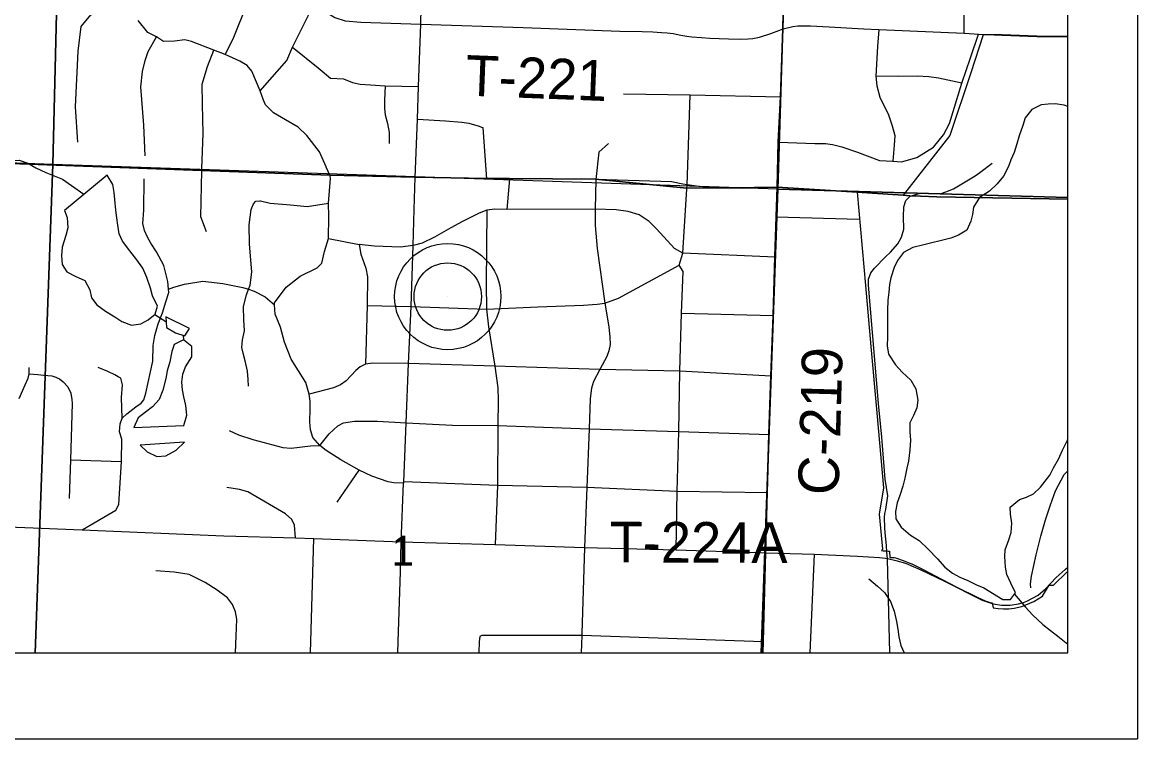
# Model space of a CAD drawing. Extents: x 0 to 34, y 0 to 22.
# Drawn here: x 8.174 to 9.735, y 14 to 15.003 of the extents above; entities that cross this region are included whole.
import ezdxf

# ---------------------------------------------------------------- set-up
doc = ezdxf.new("R2010")
doc.units = 0
for name, color, linetype in [('GM_X_City_Street', 7, 'Continuous'), ('GM_X_Corporation', 7, 'Continuous'), ('GM_X_County_Road', 7, 'Continuous'), ('GM_X_County_Road_Text', 7, 'Continuous'), ('GM_X_Major_Lake', 7, 'Continuous'), ('GM_X_Minor_Lake', 7, 'Continuous'), ('GM_X_Minor_River', 7, 'Continuous'), ('GM_X_Section_Text', 7, 'Continuous'), ('GM_X_Township_Road', 7, 'Continuous'), ('GM_X_Township_Road_Text', 7, 'Continuous'), ('GM_X_Unincorporated', 7, 'Continuous'), ('GM_X_Unincorporated_Location', 7, 'Continuous'), ('SH_Data', 7, 'Continuous')]:
    doc.layers.add(name, color=color, linetype=linetype)

msp = doc.modelspace()

# ---------------------------------------------------------------- linework, layer by layer
at = {"layer": 'GM_X_City_Street'}
for points in [[(9.3822, 14.3208), (9.385, 14.3403), (9.3814, 14.3634), (9.3768, 14.4223), (9.3723, 14.4696), (9.3581, 14.6353), (9.3583, 14.6433), (9.3616, 14.6525), (9.3665, 14.6588), (9.382, 14.675), (9.3888, 14.6815), (9.399, 14.693), (9.4045, 14.7025), (9.4075, 14.7137), (9.4072, 14.7307), (9.4075, 14.7449), (9.4105, 14.7535), (9.4164, 14.7599), (9.4304, 14.7639), (9.4497, 14.7634), (9.4584, 14.7629), (9.4664, 14.7659), (9.4769, 14.7701), (9.5076, 14.7883), (9.514, 14.7928), (9.5313, 14.8061)], [(9.5854, 14.2112), (9.585, 14.2171), (9.5864, 14.2277), (9.5926, 14.2575), (9.5992, 14.2836), (9.6061, 14.3065), (9.6127, 14.3274), (9.6201, 14.3472), (9.632, 14.3698), (9.637, 14.3752)]]:
    msp.add_lwpolyline(points, dxfattribs=at)
at = {"layer": 'GM_X_Corporation'}
for points in [[(7.1023, 20.9204), (2.837, 20.9204), (2.837, 14.1204), (9.637, 14.1204), (9.637, 20.9204), (9.4036, 20.9204), (9.4022, 20.8667), (9.2273, 20.8723), (9.1354, 20.8749), (9.124, 20.8753), (8.9858, 20.878), (8.9676, 20.8785), (8.8663, 20.881), (8.6259, 20.8892), (8.5535, 20.8914), (8.5421, 20.8915), (8.4667, 20.8934), (8.0602, 20.9055), (7.9522, 20.9084), (7.1104, 20.9188)], [(8.2409, 15.8234), (8.2165, 14.8042), (7.2089, 14.8416), (7.2356, 15.8559)], [(8.2409, 15.8234), (9.2625, 15.7858), (9.2313, 14.7696), (8.2165, 14.8042)], [(9.637, 14.7579), (9.637, 15.7721), (9.2625, 15.7858), (9.2313, 14.7696)], [(9.637, 14.234), (9.637, 14.9831), (9.5936, 14.9839), (9.545, 14.9856), (9.5186, 14.9858), (9.5013, 14.9322), (9.4722, 14.8448), (9.4066, 14.7611), (9.3424, 14.7652), (9.354, 14.6346), (9.3616, 14.5494), (9.3699, 14.4562), (9.3793, 14.3514), (9.373, 14.3145), (9.3776, 14.2655), (9.3765, 14.2634), (9.3785, 14.2633), (9.3808, 14.2632), (9.3837, 14.263), (9.3859, 14.2627), (9.3874, 14.2625), (9.388, 14.2539), (9.3941, 14.2537), (9.3957, 14.2533), (9.4001, 14.2521), (9.4091, 14.2488), (9.4162, 14.2459), (9.4188, 14.2448), (9.4337, 14.2373), (9.4613, 14.223), (9.4808, 14.2129), (9.5113, 14.1976), (9.5214, 14.193), (9.5284, 14.1908), (9.5313, 14.1902), (9.5324, 14.1835), (9.5397, 14.1824), (9.5471, 14.1819), (9.5544, 14.182), (9.5618, 14.1828), (9.5726, 14.1852), (9.5894, 14.1921), (9.6017, 14.1997), (9.6109, 14.2152), (9.617, 14.2151), (9.6364, 14.2338)], [(7.184, 14.1204), (8.1915, 14.1204), (8.2165, 14.8042), (7.2089, 14.8416)], [(8.1915, 14.1204), (9.2078, 14.1204), (9.2313, 14.7696), (8.2165, 14.8042)], [(9.2101, 14.1204), (9.637, 14.1204), (9.637, 14.7553), (9.4537, 14.7589), (9.4311, 14.7597), (9.4162, 14.7604), (9.4066, 14.7611), (9.3424, 14.7652), (9.2302, 14.7725), (9.2287, 14.7313), (9.2271, 14.6747), (9.2245, 14.5932), (9.2216, 14.5084), (9.2187, 14.4266), (9.2162, 14.3447), (9.2141, 14.2608), (9.2106, 14.1364)], [(9.2078, 14.1204), (9.637, 14.1204), (9.637, 14.7579), (9.2313, 14.7696)]]:
    msp.add_lwpolyline(points, close=True, dxfattribs=at)
for points in [[(9.24, 15.0747), (9.2383, 14.9943), (9.2348, 14.8989), (9.2316, 14.8359), (9.2302, 14.7725), (9.3424, 14.7652), (9.4066, 14.7611), (9.4162, 14.7604), (9.4311, 14.7597), (9.4537, 14.7589), (9.637, 14.7553), (9.637, 20.8621)], [(7.8005, 14.8186), (8.4248, 14.7958), (8.6041, 14.7889), (8.7233, 14.7862), (8.8234, 14.7844), (8.8557, 14.7845), (8.9761, 14.7836), (9.1036, 14.7707), (9.1664, 14.7716), (9.2302, 14.7725), (9.2316, 14.8359), (9.2348, 14.8989), (9.2383, 14.9943), (9.24, 15.0747)], [(3.0474, 14.1204), (9.2101, 14.1204), (9.2106, 14.1364), (9.2141, 14.2608), (9.2162, 14.3447), (9.2187, 14.4266), (9.2216, 14.5084), (9.2245, 14.5932), (9.2271, 14.6747), (9.2287, 14.7313), (9.2302, 14.7725), (9.1664, 14.7716), (9.1036, 14.7707), (8.9761, 14.7836), (8.8557, 14.7845), (8.8234, 14.7844), (8.7233, 14.7862), (8.6041, 14.7889), (8.4248, 14.7958), (7.8005, 14.8186)]]:
    msp.add_lwpolyline(points, dxfattribs=at)
at = {"layer": 'GM_X_County_Road'}
for p, q in [((8.7075, 14.3598), (8.709, 14.3946)), ((8.7041, 14.2756), (8.7074, 14.3578)), ((8.7074, 14.3578), (8.7075, 14.3598))]:
    msp.add_line(p, q, dxfattribs=at)
for points in [[(8.7223, 14.7411), (8.7235, 14.7857), (8.7267, 14.8676), (8.7284, 14.9133), (8.7314, 15.0006), (8.734, 15.1141), (8.7347, 15.1409), (8.7378, 15.2268), (8.7414, 15.3356), (8.7443, 15.4296), (8.7502, 15.6266), (8.7557, 15.8016)], [(9.2302, 14.7659), (9.2304, 14.772), (9.2328, 14.8353), (9.235, 14.8983), (9.2385, 14.9938), (9.2409, 15.0741), (9.2435, 15.1505), (9.2463, 15.2212), (9.247, 15.252), (9.2497, 15.2895), (9.2511, 15.3003)], [(9.2214, 14.498), (9.2218, 14.5078), (9.2247, 14.5926), (9.2273, 14.6742), (9.2289, 14.7308), (9.2302, 14.7659)], [(8.709, 14.3946), (8.711, 14.4423), (8.7143, 14.5254), (8.7181, 14.6052), (8.7209, 14.6907), (8.7223, 14.7411)], [(9.2103, 14.1204), (9.2108, 14.1359), (9.2143, 14.2602), (9.2164, 14.3442), (9.2189, 14.4261), (9.2214, 14.498)], [(6.3874, 14.359), (6.5426, 14.3539), (6.5792, 14.3522), (6.7516, 14.3468), (6.979, 14.3397), (7.0782, 14.3359), (7.2017, 14.3322), (7.361, 14.3265), (7.4872, 14.3228), (7.6653, 14.3168), (7.7263, 14.3144), (7.7972, 14.3116), (7.9431, 14.3054), (8.0388, 14.3013), (8.2574, 14.2927), (8.4556, 14.2841), (8.5559, 14.2812), (8.5818, 14.2806), (8.7041, 14.2756), (8.8353, 14.2719), (8.9607, 14.2676), (9.0887, 14.2645), (9.2143, 14.2602)], [(8.6993, 14.1204), (8.6998, 14.1358), (8.7029, 14.2341), (8.7041, 14.2756)], [(9.2143, 14.2602), (9.2822, 14.2584), (9.3426, 14.2555)], [(9.3426, 14.2555), (9.3733, 14.254), (9.3818, 14.2528)], [(9.3818, 14.2528), (9.3846, 14.2524), (9.3966, 14.2497), (9.4097, 14.2457), (9.4314, 14.2366), (9.4643, 14.2207), (9.5172, 14.1939), (9.5326, 14.189), (9.5442, 14.1872), (9.5564, 14.1872), (9.5679, 14.1888), (9.5753, 14.191)], [(9.5753, 14.191), (9.5799, 14.1925), (9.5954, 14.201), (9.6061, 14.21), (9.6208, 14.2257), (9.6332, 14.237), (9.637, 14.2401)]]:
    msp.add_lwpolyline(points, dxfattribs=at)
at = {"layer": 'GM_X_Major_Lake'}
for points in [[(9.637, 14.8852), (9.632, 14.8871), (9.6194, 14.8892), (9.6096, 14.8887), (9.5997, 14.8878), (9.5869, 14.8812), (9.5776, 14.8692), (9.5743, 14.8586), (9.5692, 14.8444), (9.5659, 14.833), (9.5619, 14.8208), (9.5575, 14.8108), (9.5539, 14.8013), (9.5472, 14.7879), (9.5383, 14.7771), (9.5274, 14.7667), (9.5135, 14.7578), (9.5049, 14.7444), (9.5036, 14.7341), (9.5014, 14.7245), (9.4959, 14.7119), (9.4842, 14.7049), (9.4733, 14.701), (9.4585, 14.6973), (9.4468, 14.6945), (9.4358, 14.6917), (9.42, 14.6877), (9.4072, 14.6807), (9.3986, 14.6695), (9.3942, 14.66), (9.3894, 14.6455), (9.3877, 14.6359), (9.3867, 14.6253), (9.3853, 14.6142), (9.3847, 14.5998), (9.3849, 14.5876), (9.3847, 14.5762), (9.3845, 14.5622), (9.3843, 14.55), (9.386, 14.5383), (9.396, 14.5236), (9.4053, 14.5135), (9.4176, 14.5022), (9.4245, 14.4898), (9.427, 14.4742), (9.426, 14.4636), (9.4213, 14.4525), (9.4161, 14.4426), (9.4159, 14.4296), (9.4168, 14.4179), (9.4162, 14.4046), (9.4142, 14.3886), (9.412, 14.379), (9.4088, 14.3649), (9.4063, 14.3539), (9.4019, 14.3405), (9.3983, 14.3302)], [(9.3983, 14.3302), (9.3958, 14.318), (9.3963, 14.3078), (9.4037, 14.2961), (9.4171, 14.2853), (9.4289, 14.2774), (9.4416, 14.2655), (9.4547, 14.252), (9.4651, 14.2403), (9.4755, 14.2317), (9.4862, 14.2262), (9.4972, 14.2214), (9.5095, 14.2155), (9.5194, 14.2115), (9.5461, 14.1951), (9.5568, 14.1949), (9.5638, 14.2045), (9.5572, 14.2181), (9.5517, 14.2302), (9.5501, 14.2404), (9.5491, 14.2552), (9.5494, 14.2647), (9.5545, 14.2784), (9.5578, 14.2888), (9.5587, 14.3021), (9.557, 14.3146), (9.5562, 14.3244), (9.5693, 14.3349), (9.5791, 14.3381), (9.5889, 14.3431), (9.599, 14.3524), (9.6121, 14.3693), (9.6172, 14.3793), (9.6239, 14.3915), (9.6298, 14.4041), (9.6361, 14.4171), (9.637, 14.4187)]]:
    msp.add_lwpolyline(points, dxfattribs=at)
at = {"layer": 'GM_X_Minor_Lake'}
for points in [[(8.2326, 14.7398), (8.2362, 14.73), (8.2371, 14.7152), (8.2346, 14.7045), (8.2292, 14.6885), (8.2282, 14.6763), (8.2295, 14.6641), (8.2357, 14.654), (8.2475, 14.6477), (8.2609, 14.6418), (8.2683, 14.6286), (8.2703, 14.6172), (8.2777, 14.6074), (8.2899, 14.5985), (8.3029, 14.5907), (8.3129, 14.5844), (8.3262, 14.5793), (8.3395, 14.581), (8.3497, 14.5864), (8.3594, 14.5945), (8.3627, 14.6056), (8.356, 14.6203), (8.3532, 14.6309), (8.3481, 14.6457), (8.3422, 14.6589), (8.3341, 14.6706), (8.3241, 14.6833), (8.3136, 14.6969), (8.3093, 14.7071), (8.3073, 14.7192), (8.306, 14.7294), (8.3047, 14.7401), (8.303, 14.7552), (8.3021, 14.7647), (8.3004, 14.7761), (8.2923, 14.7893)], [(8.2923, 14.7893), (8.2326, 14.7398)], [(8.3743, 14.5906), (8.3752, 14.5758), (8.3882, 14.5683), (8.4012, 14.5643), (8.4075, 14.5743)], [(8.4075, 14.5743), (8.3743, 14.5906)], [(8.3998, 14.4386), (8.4038, 14.4531), (8.4025, 14.4667), (8.3997, 14.4788), (8.3976, 14.4887), (8.3971, 14.4993), (8.3985, 14.5107), (8.4021, 14.5207), (8.4111, 14.5348), (8.4109, 14.5493), (8.399, 14.5586), (8.3862, 14.552), (8.3829, 14.5421), (8.38, 14.528), (8.3764, 14.515), (8.3747, 14.5043), (8.3703, 14.4883), (8.3652, 14.4749), (8.3559, 14.4649), (8.3461, 14.4572), (8.3356, 14.4494), (8.3297, 14.4357)], [(8.3297, 14.4357), (8.3998, 14.4386)], [(8.3384, 14.4111), (8.3484, 14.4017), (8.3621, 14.3951), (8.3746, 14.396), (8.3889, 14.4042), (8.4005, 14.4154)], [(8.4005, 14.4154), (8.3384, 14.4111)]]:
    msp.add_lwpolyline(points, dxfattribs=at)
at = {"layer": 'GM_X_Minor_River'}
for points in [[(8.1053, 14.8043), (8.1138, 14.8035), (8.1237, 14.8013), (8.1366, 14.8023), (8.1464, 14.8055), (8.1562, 14.8098), (8.1691, 14.8103), (8.1813, 14.806), (8.1924, 14.7993), (8.2065, 14.793), (8.216, 14.789), (8.2298, 14.7835), (8.2599, 14.7624)], [(8.359, 14.5942), (8.3747, 14.5843)], [(8.3985, 14.5652), (8.3996, 14.5581)], [(9.3587, 14.224), (9.3706, 14.2136), (9.3806, 14.205), (9.3888, 14.1922), (9.3942, 14.1789), (9.3975, 14.1642), (9.3991, 14.1535), (9.4004, 14.1429), (9.4032, 14.1308), (9.4081, 14.1204)], [(9.5626, 14.2027), (9.5778, 14.1842), (9.5878, 14.1737), (9.602, 14.1602), (9.6131, 14.1516), (9.6231, 14.1438), (9.637, 14.1324)]]:
    msp.add_lwpolyline(points, dxfattribs=at)
at = {"layer": 'GM_X_Township_Road'}
for p, q in [((8.4573, 14.9582), (8.4416, 14.9643)), ((8.8236, 14.7839), (8.8189, 14.8554)), ((8.5991, 14.8001), (8.5987, 14.801)), ((8.8525, 14.7411), (8.8559, 14.7839)), ((9.2289, 14.7308), (9.3451, 14.7273)), ((9.0964, 14.596), (9.2247, 14.5926)), ((8.2408, 14.3907), (8.3125, 14.3881)), ((8.6144, 14.3313), (8.645, 14.3762)), ((8.7075, 14.3598), (8.7074, 14.3578)), ((8.5768, 14.1204), (8.5818, 14.2806)), ((9.2822, 14.2584), (9.276, 14.1204)), ((9.3879, 14.1204), (9.3846, 14.2514)), ((8.4722, 14.1204), (8.4731, 14.1443))]:
    msp.add_line(p, q, dxfattribs=at)
for points in [[(8.4573, 14.9582), (8.4686, 14.9799), (8.5078, 15.0778), (8.5078, 15.0816), (8.5079, 15.0892), (8.5058, 15.104), (8.4977, 15.1272), (8.4941, 15.1656), (8.4936, 15.1709), (8.4912, 15.1956), (8.4914, 15.2157), (8.4924, 15.2335), (8.4921, 15.24), (8.488, 15.2491), (8.4865, 15.2545), (8.4844, 15.2621), (8.4752, 15.3067)], [(8.5066, 14.9071), (8.5438, 14.9496), (8.5519, 14.9684), (8.5815, 15.0279), (8.6179, 15.0922), (8.6348, 15.1118), (8.6409, 15.1228), (8.6499, 15.1448), (8.6528, 15.2297)], [(9.4922, 14.9879), (9.4922, 15.0663), (9.4925, 15.1419), (9.4943, 15.2165)], [(8.2515, 14.8352), (8.2479, 14.8849), (8.2517, 14.9627), (8.2559, 14.9972), (8.2693, 15.0134), (8.2826, 15.022), (8.297, 15.0302), (8.3183, 15.0398)], [(8.5815, 15.0279), (8.611, 15.01), (8.6253, 15.0053), (8.6473, 15.0035), (8.7314, 15.0006)], [(8.4416, 14.9643), (8.4105, 14.9762), (8.4011, 14.9786), (8.3865, 14.9766), (8.3712, 14.9761), (8.3612, 14.9826), (8.3494, 14.989), (8.3359, 15.0057)], [(8.7314, 15.0006), (8.8747, 14.9959), (9.0101, 14.9909), (9.0412, 14.9902), (9.0562, 14.9897), (9.0683, 14.9888), (9.0764, 14.9882), (9.0847, 14.9873), (9.0956, 14.9852), (9.104, 14.9836), (9.1107, 14.9826), (9.1242, 14.9817), (9.1358, 14.981), (9.1619, 14.9799), (9.1794, 14.9796), (9.1898, 14.9799), (9.1961, 14.9805), (9.2054, 14.9824), (9.2213, 14.9873), (9.2324, 14.9915), (9.2385, 14.9938)], [(9.2385, 14.9938), (9.2523, 14.9975), (9.2591, 14.9982), (9.2673, 14.9982), (9.2771, 14.9981), (9.3031, 14.997), (9.3518, 14.9941), (9.3725, 14.9932), (9.4922, 14.9879)], [(9.3725, 14.9932), (9.3705, 14.9693), (9.3685, 14.9279), (9.3697, 14.9143), (9.3741, 14.8985), (9.386, 14.8737), (9.3913, 14.8583), (9.3948, 14.8446), (9.3939, 14.831), (9.3921, 14.8086)], [(8.3454, 14.8164), (8.3435, 14.8593), (8.3395, 14.9126), (8.342, 14.9343), (8.3454, 14.9495), (8.3499, 14.9623), (8.3612, 14.9826)], [(9.2328, 14.8353), (9.2832, 14.8336), (9.2981, 14.8333), (9.3079, 14.8321), (9.3207, 14.8286), (9.3428, 14.8214), (9.3736, 14.8098), (9.3921, 14.8086), (9.4041, 14.8077), (9.426, 14.8137), (9.4492, 14.8283), (9.4631, 14.8455), (9.4717, 14.8614), (9.489, 14.9177), (9.5009, 14.9535), (9.5122, 14.9866)], [(9.4922, 14.9879), (9.5062, 14.987), (9.5122, 14.9866)], [(9.5122, 14.9866), (9.5452, 14.9851), (9.5938, 14.9833), (9.637, 14.9826)], [(8.4251, 14.7982), (8.4268, 14.8475), (8.4256, 14.8885), (8.4255, 14.9166), (8.433, 14.9412), (8.4416, 14.9643)], [(8.5987, 14.801), (8.5895, 14.8218), (8.5717, 14.8445), (8.5599, 14.8564), (8.5421, 14.8667), (8.5254, 14.8766), (8.514, 14.8874), (8.5111, 14.8943), (8.5066, 14.9071), (8.4948, 14.9347), (8.4884, 14.9426), (8.478, 14.9485), (8.4573, 14.9582)], [(8.5519, 14.9684), (8.5876, 14.9393), (8.6048, 14.9247), (8.6232, 14.9239), (8.6357, 14.9189), (8.6463, 14.9165), (8.661, 14.9156), (8.6817, 14.9143), (8.7284, 14.9133)], [(9.489, 14.9177), (9.4561, 14.9247), (9.4428, 14.9266), (9.4263, 14.9278), (9.3996, 14.9274), (9.3685, 14.9279)], [(8.6817, 14.9143), (8.6807, 14.8939), (8.6807, 14.8826), (8.6816, 14.8737), (8.6846, 14.8616), (8.6872, 14.8489), (8.6873, 14.8333)], [(9.235, 14.8983), (9.1083, 14.9013), (9.0152, 14.9024)], [(9.0929, 14.6633), (9.0984, 14.6799), (9.1038, 14.7701), (9.1042, 14.7756), (9.1083, 14.9013)], [(8.7267, 14.8676), (8.7659, 14.8652), (8.7887, 14.8631), (8.7986, 14.8617), (8.8132, 14.8577), (8.8189, 14.8554)], [(8.9942, 14.8336), (8.9808, 14.8215), (8.9763, 14.783)], [(8.4312, 14.7099), (8.4233, 14.7306), (8.425, 14.7953), (8.4251, 14.7982)], [(8.7074, 14.3578), (8.6937, 14.3584), (8.6855, 14.3598), (8.6628, 14.3677), (8.645, 14.3762), (8.6194, 14.3904), (8.599, 14.4035), (8.5899, 14.4107), (8.5803, 14.4219), (8.577, 14.4328), (8.576, 14.4439), (8.5763, 14.4614), (8.5766, 14.4729), (8.5753, 14.4824), (8.5704, 14.4989), (8.5501, 14.5317), (8.5404, 14.5552), (8.5348, 14.5761), (8.5273, 14.5943), (8.5267, 14.6076), (8.5266, 14.6103), (8.5429, 14.6322), (8.5626, 14.6477), (8.5865, 14.6594), (8.593, 14.6661), (8.5964, 14.6824), (8.6021, 14.7003), (8.6027, 14.7313), (8.6023, 14.75), (8.6052, 14.7844), (8.6043, 14.7884), (8.5991, 14.8001)], [(8.2574, 14.2927), (8.3047, 14.3203), (8.3087, 14.3282), (8.3125, 14.3881), (8.3129, 14.4193), (8.3096, 14.4298), (8.3104, 14.4408), (8.3134, 14.4489), (8.3199, 14.4548), (8.3325, 14.4646), (8.34, 14.4699), (8.3438, 14.4748), (8.3465, 14.4839), (8.3565, 14.5286), (8.3566, 14.5506), (8.3589, 14.5646), (8.3639, 14.5809), (8.37, 14.5964), (8.3746, 14.6116), (8.3788, 14.6248), (8.3784, 14.6293), (8.3773, 14.6404), (8.3718, 14.6628), (8.3616, 14.6818), (8.3533, 14.6939), (8.3488, 14.7023), (8.3447, 14.7118), (8.3421, 14.7213), (8.3439, 14.74), (8.3443, 14.7842)], [(9.0983, 14.7767), (9.0825, 14.7797), (8.9763, 14.783), (8.8559, 14.7839), (8.8236, 14.7839)], [(8.9763, 14.783), (8.9756, 14.7416), (8.9755, 14.7187), (8.9783, 14.6864), (8.9891, 14.61), (8.9944, 14.5766), (8.9961, 14.5625), (8.9965, 14.5519), (8.9948, 14.5434), (8.9916, 14.5352), (8.9821, 14.517), (8.973, 14.5003), (8.9703, 14.4909), (8.9685, 14.4764), (8.9671, 14.434), (8.9639, 14.3518), (8.9607, 14.2676), (8.9568, 14.1475)], [(9.2304, 14.772), (9.1811, 14.7706), (9.1666, 14.771), (9.1381, 14.772), (9.1206, 14.7733), (9.1042, 14.7756), (9.0983, 14.7767)], [(8.4902, 14.4936), (8.4895, 14.5031), (8.4888, 14.5149), (8.4854, 14.5293), (8.4825, 14.5399), (8.481, 14.5479), (8.4818, 14.5585), (8.4845, 14.571), (8.4838, 14.5865), (8.4831, 14.6051), (8.4873, 14.6218), (8.4901, 14.6294), (8.4923, 14.635), (8.495, 14.6532), (8.4914, 14.693), (8.4911, 14.7196), (8.4938, 14.7412), (8.4972, 14.7488), (8.5003, 14.7525), (8.5059, 14.7533), (8.5069, 14.7531), (8.5207, 14.7498), (8.549, 14.7478), (8.5725, 14.7451), (8.6023, 14.75)], [(9.2273, 14.6742), (9.0984, 14.6799), (9.0867, 14.6866), (9.0615, 14.7141), (9.0511, 14.7242), (9.0372, 14.7334), (9.0215, 14.7384), (9.0048, 14.7406), (8.9756, 14.7416), (8.8525, 14.7411), (8.8349, 14.7417), (8.824, 14.74), (8.8133, 14.7359), (8.7898, 14.7242), (8.7735, 14.7152), (8.7504, 14.7024), (8.7334, 14.6939), (8.7209, 14.6907), (8.7029, 14.6885), (8.6667, 14.6896), (8.6452, 14.6921)], [(8.824, 14.74), (8.8227, 14.6364), (8.8235, 14.6017), (8.826, 14.5768), (8.8351, 14.5216), (8.8391, 14.4915), (8.8398, 14.4735), (8.8394, 14.4387), (8.8387, 14.3548), (8.8353, 14.2719)], [(8.6021, 14.7003), (8.6452, 14.6921), (8.6474, 14.6784), (8.6545, 14.6588), (8.6569, 14.6468), (8.6562, 14.6068), (8.6538, 14.5246)], [(8.6562, 14.6068), (8.7181, 14.6052), (8.8235, 14.6017), (8.895, 14.6046), (8.9591, 14.6071), (8.9784, 14.6083), (8.9891, 14.61), (9.0083, 14.6171), (9.0929, 14.6633)], [(9.0964, 14.596), (9.0988, 14.6543), (9.0929, 14.6633)], [(8.3784, 14.6293), (8.3856, 14.6324), (8.4004, 14.6365), (8.4261, 14.6406), (8.4541, 14.6374), (8.4824, 14.632), (8.4901, 14.6294), (8.4979, 14.6267), (8.5134, 14.619), (8.5267, 14.6076)], [(9.0887, 14.2645), (9.0902, 14.3463), (9.0926, 14.4301), (9.0939, 14.5145), (9.0964, 14.596)], [(9.2218, 14.5078), (9.0939, 14.5145), (8.9821, 14.517), (8.8351, 14.5216), (8.7143, 14.5254), (8.6643, 14.5261), (8.6538, 14.5246), (8.6463, 14.5209), (8.6406, 14.5155), (8.6268, 14.501), (8.6189, 14.4958), (8.6094, 14.4915), (8.5753, 14.4824)], [(8.1693, 14.4766), (8.1741, 14.4883), (8.1775, 14.4954), (8.1816, 14.505), (8.1831, 14.5109), (8.1833, 14.5139), (8.1832, 14.5199)], [(8.1831, 14.5109), (8.1953, 14.51), (8.2039, 14.5093), (8.215, 14.5081), (8.2207, 14.5062), (8.2224, 14.5056), (8.2255, 14.5039), (8.2308, 14.4999), (8.2371, 14.4928), (8.2415, 14.4841), (8.2431, 14.4751), (8.2434, 14.4693), (8.2408, 14.3907), (8.239, 14.3365)], [(8.3134, 14.4489), (8.3125, 14.4779), (8.3137, 14.4958), (8.3114, 14.5049), (8.3077, 14.5068), (8.3031, 14.5098), (8.2933, 14.5144), (8.2797, 14.5198)], [(8.5899, 14.4107), (8.6029, 14.4268), (8.6151, 14.4384), (8.6233, 14.4423), (8.6385, 14.4449), (8.671, 14.4446), (8.711, 14.4423), (8.7759, 14.4393), (8.8394, 14.4387), (8.9671, 14.434), (9.0926, 14.4301), (9.2189, 14.4261)], [(8.4632, 14.4318), (8.4764, 14.4255), (8.4964, 14.419), (8.5382, 14.4078), (8.55, 14.4068), (8.577, 14.4101), (8.5899, 14.4107)], [(8.5559, 14.2812), (8.5546, 14.2989), (8.5507, 14.3072), (8.5418, 14.3151), (8.4892, 14.3456), (8.4777, 14.3489), (8.4599, 14.3519)], [(9.2164, 14.3442), (9.0902, 14.3463), (8.9639, 14.3518), (8.8387, 14.3548), (8.7075, 14.3598)], [(9.3839, 14.2615), (9.3833, 14.2705), (9.3816, 14.2882), (9.3809, 14.2954), (9.3803, 14.3099), (9.3812, 14.3156), (9.3822, 14.3208)], [(9.3846, 14.2514), (9.3846, 14.2524), (9.3839, 14.2615)], [(8.4731, 14.1443), (8.4735, 14.1553), (8.4737, 14.1676), (8.4719, 14.1779), (8.4679, 14.188), (8.4606, 14.1973), (8.4462, 14.2082), (8.4294, 14.2188), (8.4072, 14.2299), (8.3863, 14.2335), (8.3605, 14.2352)], [(8.9568, 14.1475), (8.9568, 14.1445), (8.956, 14.1204)], [(8.8169, 14.1447), (8.8139, 14.1432), (8.8131, 14.1364), (8.8126, 14.1204)], [(9.2108, 14.1359), (8.9568, 14.1445), (8.8169, 14.1447)]]:
    msp.add_lwpolyline(points, dxfattribs=at)
at = {"layer": 'GM_X_Unincorporated'}
for radius in [0.0744, 0.0472]:
    msp.add_circle((8.7691, 14.6191), radius, dxfattribs=at)
at = {"layer": 'GM_X_Unincorporated_Location'}
msp.add_line((8.7691, 14.6191), (8.7691, 14.6191), dxfattribs=at)
at = {"layer": 'SH_Data'}
for p in [(9.7349, 21.0001), (2.7349, 14.0001)]:
    msp.add_line(p, (9.7349, 14.0001), dxfattribs=at)

# ---------------------------------------------------------------- texts
at = {"layer": 'GM_X_County_Road_Text'}
msp.add_text('C-219', height=0.05682, rotation=88.3507, dxfattribs=at).set_placement((9.3161, 14.3406))
at = {"layer": 'GM_X_Section_Text'}
msp.add_text('1', height=0.0419, rotation=0, dxfattribs=at).set_placement((8.6907, 14.2425))
at = {"layer": 'GM_X_Township_Road_Text'}
for s, rotation, p in [('T-221', 357.7546, (8.7932, 14.9006)), ('T-224A', 359.7838, (8.9956, 14.2471))]:
    msp.add_text(s, height=0.05682, rotation=rotation, dxfattribs=at).set_placement(p)

doc.saveas('drawing.dxf')
